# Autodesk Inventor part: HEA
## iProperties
Author: Jan-Steinar
Shininess: 20.0
PropertySet Name: _Private Model Information
Created: 2001-01
Part Number: HEA
Document SubType Name: Modeling
Designer: Jan-Steinar
Control State: 0
Master: False
Checked Out: False
PropertySet Name: Design Tracking Control
Density: 0.0
Volumn: 0.0
Area: 0.0
PropertySet Name: Model Information
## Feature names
1. Extrusion1
